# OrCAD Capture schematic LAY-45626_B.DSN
size A4; title: Generic expansion board; rev: 2; note: PCB2461-2
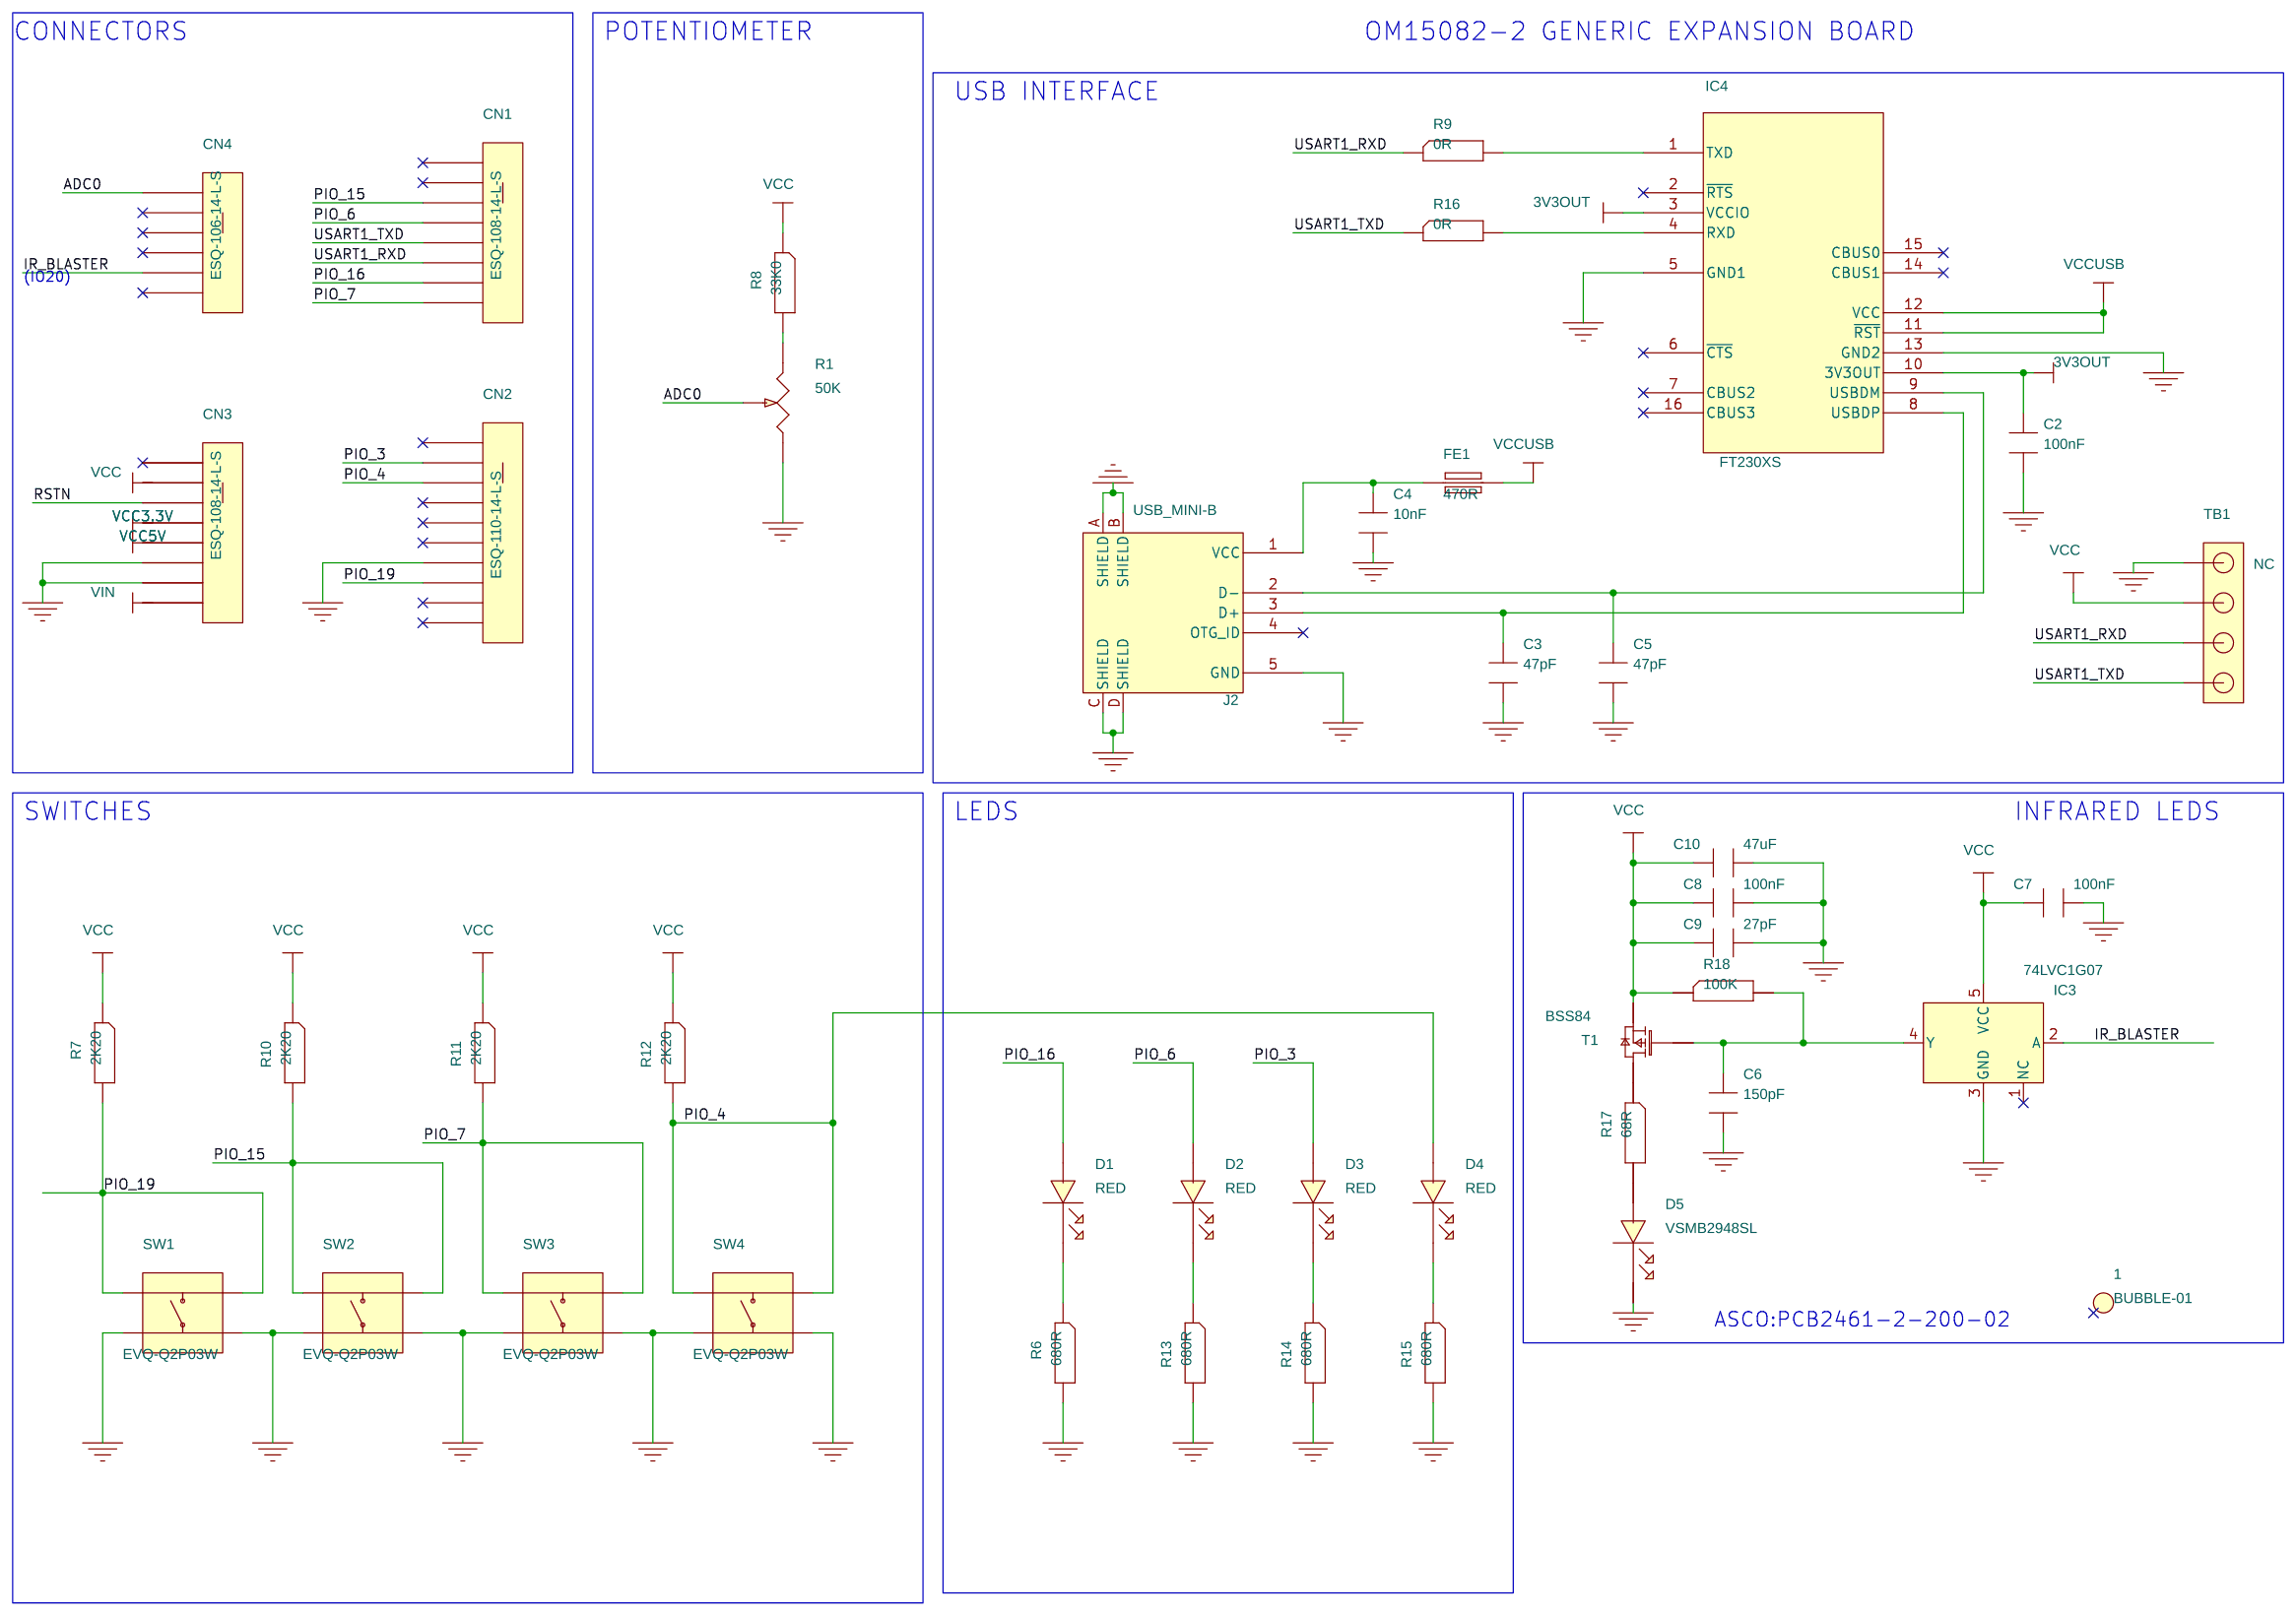
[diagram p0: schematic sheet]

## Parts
1  BUBBLE-01  [BUBBLE_DIAM8]
C2  100nF  [C0603]
C3  47pF  [C0603]
C4  10nF  [C0603]
C5  47pF  [C0603]
C6  150pF  [C0603]
C7  100nF  [C0603]
C8  100nF  [C0603]
C9  27pF  [C0603]
C10  47uF  [C0805]
CN1  ESQ-108-14-L-S  [ESQ-108-14-L-S]
CN2  ESQ-110-14-L-S  [ESQ-110-14-L-S]
CN3  ESQ-108-14-L-S  [ESQ-108-14-L-S]
CN4  ESQ-106-14-L-S  [ESQ-106-14-L-S]
D1  RED  [LED_0603_A_K]
D2  RED  [LED_0603_A_K]
D3  RED  [LED_0603_A_K]
D4  RED  [LED_0603_A_K]
D5  VSMB2948SL  [LED_VSMB2948SL]
FE1  470R  [blm18]
IC3  74LVC1G07  [SOT353_065]
IC4  FT230XS  [jedec_mo137_ab_ssop16]
J2  USB_MINI-B  [usb_mini-b]
R1  50K  [TRIM_63M_T607]
R6  680R  [R0603]
R7  2K20  [R0603]
R8  33K0  [R0603]
R9  0R  [R0603]
R10  2K20  [R0603]
R11  2K20  [R0603]
R12  2K20  [R0603]
R13  680R  [R0603]
R14  680R  [R0603]
R15  680R  [R0603]
R16  0R  [R0603]
R17  68R  [R0603]
R18  100K  [R0603]
SW1  EVQ-Q2P03W  [BP_EVQQ2]
SW2  EVQ-Q2P03W  [BP_EVQQ2]
SW3  EVQ-Q2P03W  [BP_EVQQ2]
SW4  EVQ-Q2P03W  [BP_EVQQ2]
T1  BSS84  [SOT23_1G_2S_3D]
TB1  NC  [bar_1x4_MD]

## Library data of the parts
1 = BUBBLE: Designation: Printed Circuit Board : OM15082-2 (NXP : Generic expansion board); Manufacturer_reference: PCB2461-2; Part Number: 0-CI-001585; Part Type: BUBBLE-001_CI; Supplier: ASCO
C2 C7 C8 = CAPA: Alt_Symbols: 0603C; Designation: Capacitor 0603 100nF 10% 50V X7R (-55°C+125°C); Gamme: X7R; Package: 603; Part Number: 0-00-300224; Temp: (-55°C+125°C); Tension: 50V; Tol: 10%
C3 C5 = CAPA: Alt_Symbols: 0603C; Designation: Capacitor 0603 47pF 5% 50V COG/NPO (-55°C+125°C); Gamme: COG/NPO; Package: 603; Part Number: 0-00-300412; Temp: (-55°C+125°C); Tension: 50V; Tol: 5%
C4 = CAPA: Alt_Symbols: 0603C; Designation: Capacitor 0603 10nF 10% 50V X7R (-55°C+125°C); Gamme: X7R; Package: 603; Part Number: 0-00-300244; Temp: (-55°C+125°C); Tension: 50V; Tol: 10%
C6 = CAPA: Alt_Symbols: 0603C; Designation: Capacitor 0603 150pF 5% 100V COG/NPO (-55°C+125°C); Gamme: COG/NPO; Package: 603; Part Number: 0-00-300280; Temp: (-55°C+125°C); Tension: 100V; Tol: 5%
C9 = CAPA: Designation: Capacitor 0603 27pF 5% 50V; MANUFACTURER_REFERENCE: KEMET (C0603C270J5GACTU), SYFER TECHNOLOGY (0603J050 0270JC@), VISHAY (VJ0603A270JXAAT); Package: 603; Part Number: 0-00-300356B; Supplier: DIGIKEY CORPORATION; Tension: 50V; Tol: 5%
C10 = CAPA: Alt_Symbols: 0805C; Designation: Capacitor 0805 47uF 20% 6.3V X5R (-55°C+85°C); Gamme: X5R; Package: 805; Part Number: 0-00-300617; Temp: (-55°C+85°C); Tension: 6.3V; Tol: 20%
CN1 CN3 = HEADER_8P: Designation: SOCKET, 1ROW, 8WAY Vertical ESQ-108-14-L-S; Manufacturer_reference: SAMTEC (ESQ-108-14-L-S); Package: 2MM54; Part Number: 0-00-203814; Part Type: CON_2MM54
CN2 = HEADER_10P: Designation: SOCKET, 1ROW, 10WAY Vertical ESQ-110-14-L-S; Manufacturer_reference: SAMTEC (ESQ-110-14-L-S); Package: 2MM54; Part Number: 0-00-204059; Part Type: CON_2MM54
CN4 = HEADER_6P: Designation: SOCKET, 1ROW, 6WAY Vertical ESQ-106-14-L-S; Manufacturer_reference: SAMTEC (ESQ-106-14-L-S); Package: 2MM54; Part Number: 0-00-203813; Part Type: CON_2MM54
D1-D4 = LED: Designation: LED SMD 0603 RED (0603); Manufacturer_reference: AVAGO TECHNOLOGIES (ASMT-RR45-AQ902); Package: 0603; Part Number: 0-00-002131A
D5 = LED_VSMB2948G: Designation: EMITTER IR RADIAL; Manufacturer_reference: VISHAY(VSMB2948SL); Package: LED_CMS; Part Number: 0-00-002807; Part Type: LED_EMITTING
FE1 = FERRITE_2: Designation: Ferrite Bead (470R - 100MHz); Manufacturer_reference: MURATA (BLM18PG471SN1D); Package: BLM18; Part Number: 0-00-000446A; Part Type: FERRITE
IC3 = 74LVC1G07: Designation: Integrated Circuit Buffer 74LVC1G07GW (TSSOP5) (SOT353-1); Manufacturer_reference: NXP (74LVC1G07GW,125); Package: SOT353-1; Part Number: 0-00-400213; Part Type: IC; Temp: (-40°C to +125°C)
IC4 = FT230XS: Designation: Integrated Circuit FT230XS (SSOP-16); Manufacturer_reference: FTDI Chip (FT230XS), FTDI Chip (FT230XS-R), FTDI Chip (FT230XS-U); Package: SSOP-16; Part Number: 0-00-400790; Part Type: IC
J2 = USB_MINI-B: Designation: Mini-B USB connector (SMD); Manufacturer_reference: MOLEX (0675031020); Part Number: 0-00-202936; Part Type: USB
R1 = POT: Designation: Trimmer 50K 10% 100ppm - M63M503KB30T607; Manufacturer_reference: VISHAY (M63M503KB30T607); Package: TRIMMER; Part Number: 0-00-305094; Part Type: TRIMMER
R6 R13-R15 = RES: Alt_Symbols: 0603R; Designation: Resistor 0603 680R 1% 100ppm -; PACKAGE: 603; PPM: 100ppm; Part Number: 0-00-302752; TOL: 1%; Type: CMS
R7 R10-R12 = RES: Alt_Symbols: 0603R; Designation: Resistor 0603 2K20 1% 100ppm -; PACKAGE: 603; PPM: 100ppm; Part Number: 0-00-302487; TOL: 1%; Type: CMS
R8 = RES: Alt_Symbols: 0603R; Designation: Resistor 0603 33K0 1% 100ppm -; PACKAGE: 603; PPM: 100ppm; Part Number: 0-00-302533; TOL: 1%; Type: CMS
R9 R16 = RES: Designation: Resistor 0603 0R 1% 100ppm -; MANUFACTURER_REFERENCE: YAGEO (PHYCOMP) (RC0603FR-070RL); PACKAGE: 603; PPM: 100ppm; Part Number: 0-00-302172H; SUPPLIER: FARNELL; TOL: 1%
R17 = RES: Alt_Symbols: 0603R; Designation: Resistor 0603 68R 1% 100ppm -; PACKAGE: 603; PPM: 100ppm; Part Number: 0-00-302760; TOL: 1%; Type: CMS
R18 = RES: Designation: Resistor 0603 100K 5% 200ppm -; MANUFACTURER_REFERENCE: MULTICOMP (MC0063W06035100K); PACKAGE: 603; PPM: 200ppm; Part Number: 0-00-302180C; SUPPLIER: FARNELL; TOL: 5%
SW1-SW4 = BP_EVQQ2: Designation: Switch tactile SPST - EVQ-Q2P03W (EVQQ2); Manufacturer_reference: PANASONIC (EVQ-Q2P03W); Package: EVQQ2; Part Number: 0-00-001838; Part Type: COMMUTATOR
T1 = MOSFET_G1_S2_D3: Designation: Transistor BSS84 (SOT-23); Manufacturer_reference: N	XP(BSS84,215); Package: SOT-23; Part Number: PN-BSS84,215; Part Type: TRANSISTOR_MOSFET
TB1 = bar_1x4_MD: Designation: !!! NOT CONNECTED !!! Header,Single,Row,Straight,4 pin,Pitch:2.54; Package: 2MM54; Part Number: 0-00-200119_NC; Part Type: CON_2MM54

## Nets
3V3OUT: C2.1 IC4.3(VCCIO) IC4.10(3V3OUT)
GND: C2.2 C3.2 C4.2 C5.2 C6.2 C7.2 C8.2 C9.2 C10.2 CN2.7 CN3.6 CN3.7 D5.K IC3.3(GND) IC4.5(GND1) IC4.13(GND2) J2.5(GND) J2.A(SHIELD) J2.B(SHIELD) J2.C(SHIELD) J2.D(SHIELD) R1.1 R6.2 R13.2 R14.2 R15.2 SW1.A SW1.AP SW2.A SW2.AP SW3.A SW3.AP SW4.A SW4.AP TB1.1
VCC: C7.1 C8.1 C9.1 C10.1 CN3.2 IC3.5(VCC) R7.1 R8.1 R10.1 R11.1 R12.1 R18.1 T1.2(S) TB1.2
VCC3.3V: CN3.4
VCC5V: CN3.5
VCCUSB: FE1.2 IC4.11(~{RST}) IC4.12(VCC)
VIN: CN3.8
ADC0: CN4.1 R1.2
IR_BLASTER: CN4.5 IC3.2(A)
PIO_3: CN2.2 D3.A
PIO_4: CN2.3 D4.A R12.2 SW4.B SW4.BP
PIO_6: CN1.4 D2.A
PIO_7: CN1.8 R11.2 SW3.B SW3.BP
PIO_15: CN1.3 R10.2 SW2.B SW2.BP
PIO_16: CN1.7 D1.A
PIO_19: CN2.8 R7.2 SW1.B SW1.BP
RSTN: CN3.3
USART1_RXD: CN1.6 R9.1 TB1.3
USART1_TXD: CN1.5 R16.1 TB1.4
N01844: R1.3 R8.2
N09961: D1.K R6.1
N10143: D2.K R13.1
N10285: D3.K R14.1
N10430: D4.K R15.1
N12889: C4.1 FE1.1 J2.1(VCC)
N15485: C5.1 IC4.9(USBDM) J2.2(D-)
N15494: C3.1 IC4.8(USBDP) J2.3(D+)
N16219: IC4.1(TXD) R9.2
N16257: IC4.4(RXD) R16.2
N23077: C6.1 IC3.4(Y) R18.2 T1.1(G)
N49761: D5.A R17.2
N49762: R17.1 T1.3(D)

Not connected (* = marked no-connect by the designer): 1 1*; CN1 1* 2*; CN2 1* 4* 5* 6* 9* 10*; CN3 1*; CN4 2* 3* 4* 6*; IC3 1(NC)*; IC4 2(~{RTS})* 6(~{CTS})* 7(CBUS2)* 14(CBUS1)* 15(CBUS0)* 16(CBUS3)*; J2 4(OTG_ID)*

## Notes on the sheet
- CONNECTORS
- POTENTIOMETER
- OM15082-2 GENERIC EXPANSION BOARD
- USB INTERFACE
- (IO20)
- SWITCHES
- LEDS
- INFRARED LEDS
- ASCO:PCB2461-2-200-02
